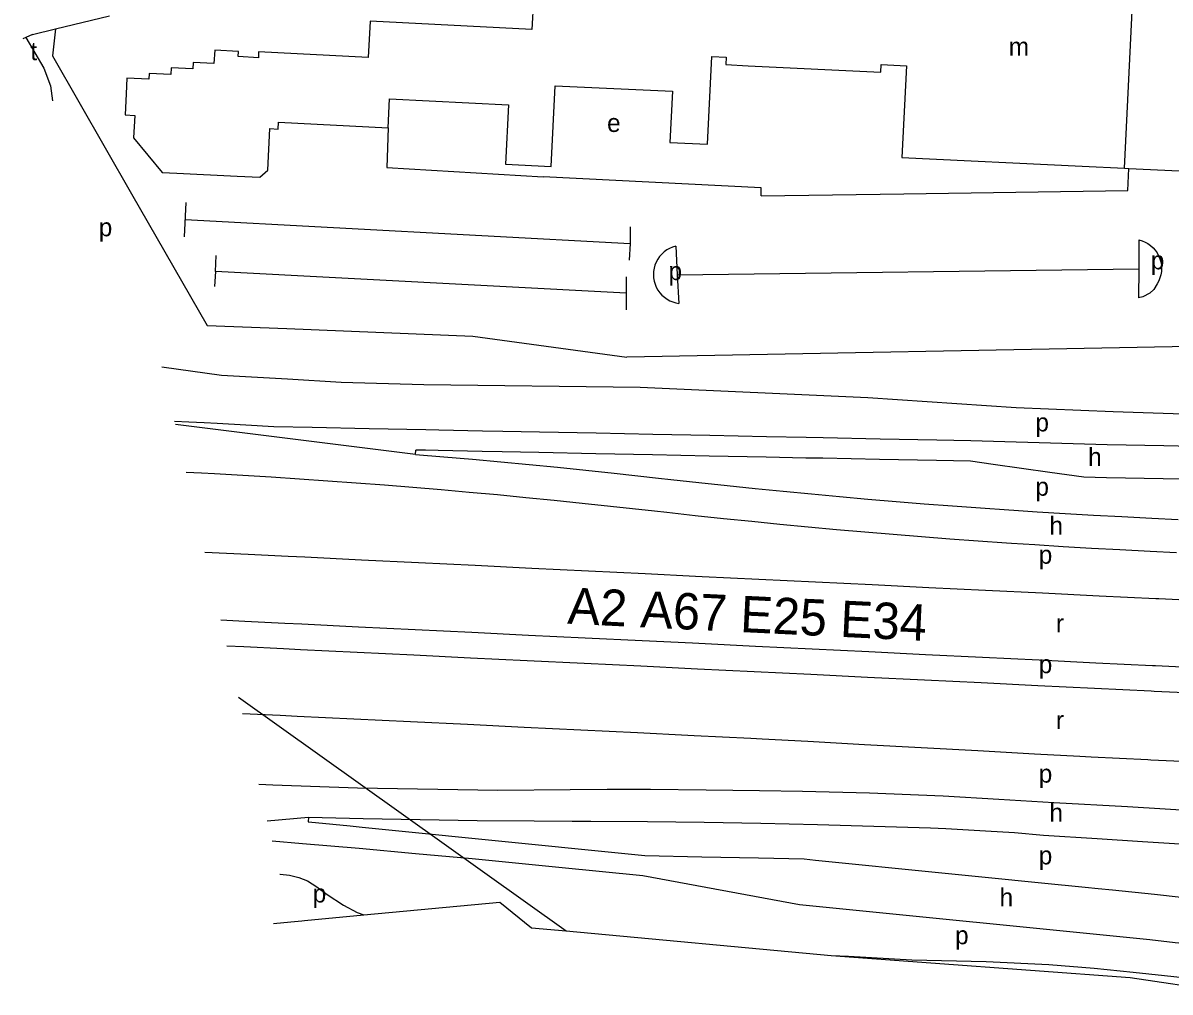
# Model space of a CAD drawing. Extents: x 161093 to 163177, y 379000 to 380904.
# Drawn here: x 161198.6 to 161451, y 379514.3 to 379727.5 of the extents above; entities that cross this region are included whole.
import ezdxf

# ---------------------------------------------------------------- set-up
doc = ezdxf.new("R2010")
doc.units = 0
for name, color, linetype in [('BLT_Basislijn', 7, 'Continuous'), ('BLT_Bebouwing', 7, 'Continuous'), ('BLT_Centroide', 7, 'Continuous'), ('BLT_Gemeentegrens', 7, 'Continuous'), ('BLT_Hoogspanningsmast_en_leidingen', 7, 'Continuous'), ('BLT_Onderdoorgang_en_onderverdeling', 7, 'Continuous'), ('BLT_Straatnaam_hoofdweg', 7, 'Continuous'), ('BLT_Vlakafsluiter', 7, 'Continuous')]:
    doc.layers.add(name, color=color, linetype=linetype)

msp = doc.modelspace()

# ---------------------------------------------------------------- linework, layer by layer
at = {"layer": 'BLT_Basislijn'}
for p, q in [((161205.69, 379726.17), (161217.61, 379729.09)), ((161200.69, 379724.95), (161205.69, 379726.17)), ((161199.17, 379724.28), (161198.56, 379724)), ((161200.69, 379724.95), (161199.17, 379724.28)), ((161361.02, 379689.46), (161392.42, 379689.88)), ((161234.4, 379688.04), (161234.08, 379680.46)), ((161234.28, 379684.25), (161332.2, 379679.02)), ((161332.22, 379682.62), (161332.2, 379679.02)), ((161332.2, 379679.02), (161332.01, 379675.35)), ((161342.24, 379678.39), (161342.59, 379672.11)), ((161444.19, 379679.79), (161444.16, 379673.43)), ((161342.59, 379672.11), (161444.16, 379673.43)), ((161444.16, 379673.43), (161444.12, 379667.07)), ((161240.91, 379672.82), (161240.71, 379669.5)), ((161331.36, 379671.66), (161331.34, 379668.05)), ((161342.59, 379672.11), (161342.93, 379665.82)), ((161331.34, 379668.05), (161331.32, 379664.43)), ((161284.94, 379632.59), (161285.02, 379633.53))]:
    msp.add_line(p, q, dxfattribs=at)
for points in [[(161205.69, 379726.17), (161205.1, 379720.28), (161222.47, 379689.88)], [(161199.17, 379724.28), (161203.13, 379717.53), (161204.65, 379713.67), (161205.1, 379710.37)], [(161278.96, 379704.45), (161278.68, 379695.69), (161313.06, 379693.67)], [(161361.02, 379689.46), (161361.02, 379691.26), (161313.06, 379693.67)], [(161392.42, 379689.88), (161441.74, 379690.61), (161441.93, 379695.52)], [(161222.47, 379689.88), (161239.14, 379660.92), (161256.65, 379660.27)], [(161342.24, 379678.39), (161341.55, 379678.19), (161340.89, 379677.91), (161340.27, 379677.56), (161339.69, 379677.14), (161339.16, 379676.66), (161338.69, 379676.12), (161338.28, 379675.54), (161337.93, 379674.91), (161337.67, 379674.25), (161337.47, 379673.56), (161337.35, 379672.86), (161337.32, 379672.14), (161337.36, 379671.43), (161337.48, 379670.72), (161337.68, 379670.04), (161337.96, 379669.38), (161338.31, 379668.75), (161338.72, 379668.17), (161339.2, 379667.64), (161339.73, 379667.16), (161340.32, 379666.75), (161340.94, 379666.4), (161341.61, 379666.13), (161342.29, 379665.93), (161342.93, 379665.82)], [(161444.19, 379679.79), (161444.88, 379679.59), (161445.54, 379679.31), (161446.17, 379678.96), (161446.75, 379678.54), (161447.29, 379678.06), (161447.77, 379677.52), (161448.18, 379676.93), (161448.53, 379676.3), (161448.8, 379675.64), (161449, 379674.95), (161449.12, 379674.24), (161449.17, 379673.52), (161449.13, 379672.8), (161449.01, 379672.1), (161448.82, 379671.4), (161448.54, 379670.74), (161448.2, 379670.11), (161447.45, 379668.85), (161446.59, 379668.04), (161445.08, 379667.22), (161444.12, 379667.07)], [(161331.34, 379668.05), (161240.91, 379672.82), (161241.1, 379676.36)], [(161256.65, 379660.27), (161297.56, 379658.59), (161331.45, 379654.01)], [(161455.37, 379656.3), (161331.45, 379654.01)], [(161229.14, 379651.85), (161242.26, 379650.05), (161256.79, 379649.21)], [(161256.79, 379649.21), (161268.61, 379648.52), (161286.79, 379647.95), (161334.43, 379647.41), (161384.55, 379645.12), (161417.14, 379642.88), (161438.53, 379642.04), (161456.14, 379641.47), (161472.44, 379640.15), (161475.32, 379639.71), (161477.25, 379638.79)], [(161462.19, 379634.21), (161449.69, 379634.47), (161437.2, 379634.72), (161432.2, 379634.82), (161424.7, 379635.04), (161412.21, 379635.42), (161407.21, 379635.57), (161399.71, 379635.72), (161387.21, 379635.97), (161374.71, 379636.23), (161370.93, 379636.3), (161362.22, 379636.48), (161349.72, 379636.73), (161337.22, 379636.98), (161324.72, 379637.23), (161312.23, 379637.48), (161304.15, 379637.65), (161299.73, 379637.74), (161290.07, 379637.93), (161287.23, 379637.99), (161274.73, 379638.24), (161262.24, 379638.49), (161253.81, 379638.66), (161247.61, 379639.04), (161241.33, 379639.4), (161238.46, 379639.53), (161235.05, 379639.68), (161231.94, 379639.81)], [(161284.94, 379632.59), (161291.23, 379632.07), (161297.48, 379631.52), (161303.73, 379630.95), (161309.97, 379630.36), (161316.22, 379629.75), (161322.46, 379629.11), (161328.7, 379628.45), (161338.41, 379627.37), (161341.15, 379627.06), (161347.34, 379626.38), (161353.53, 379625.72), (161359.72, 379625.09), (161365.92, 379624.48), (161372.11, 379623.89), (161378.31, 379623.32), (161384.51, 379622.78), (161390.72, 379622.25), (161396.92, 379621.75), (161403.13, 379621.28), (161409.34, 379620.83), (161415.55, 379620.4), (161416.69, 379620.32), (161421.76, 379619.99), (161427.97, 379619.6), (161434.19, 379619.24), (161440.4, 379618.9), (161447.03, 379618.57), (161452.86, 379618.28)], [(161486.32, 379626.53), (161483.91, 379626.53), (161474.54, 379626.71), (161462.05, 379626.97), (161449.55, 379627.22), (161437.05, 379627.47), (161432.05, 379627.57), (161424.57, 379628.62), (161412.1, 379630.37), (161407.12, 379631.07), (161399.62, 379631.22), (161387.12, 379631.48), (161374.62, 379631.73), (161370.84, 379631.8), (161362.13, 379631.98), (161349.63, 379632.23), (161337.13, 379632.48), (161324.63, 379632.73), (161312.14, 379632.99), (161304.06, 379633.15), (161299.64, 379633.24), (161289.98, 379633.43), (161287.14, 379633.49), (161285.02, 379633.53)], [(161234.52, 379628.71), (161237.86, 379628.53), (161240.72, 379628.37), (161246.95, 379628.01), (161253.19, 379627.63), (161259.42, 379627.22), (161265.66, 379626.79), (161271.89, 379626.34), (161278.12, 379625.87), (161284.35, 379625.37), (161290.58, 379624.85), (161296.8, 379624.3), (161303.02, 379623.74), (161309.24, 379623.15), (161315.46, 379622.53), (161321.68, 379621.9), (161327.89, 379621.24), (161337.56, 379620.17), (161340.31, 379619.86), (161346.53, 379619.18), (161352.74, 379618.52), (161358.96, 379617.88), (161365.18, 379617.26), (161371.41, 379616.67), (161377.63, 379616.1), (161383.86, 379615.55), (161390.09, 379615.03), (161396.32, 379614.53), (161402.56, 379614.05), (161408.79, 379613.6), (161415.03, 379613.16), (161416.17, 379613.09), (161421.27, 379612.75), (161427.51, 379612.37), (161433.75, 379612), (161439.99, 379611.66), (161446.65, 379611.33), (161452.47, 379611.04)], [(161238.61, 379611.1), (161248.14, 379610.64), (161256.91, 379610.21), (161260.62, 379610.03), (161273.11, 379609.42), (161285.59, 379608.81), (161298.08, 379608.21), (161310.56, 379607.6), (161323.05, 379606.99), (161335.53, 379606.38), (161346.62, 379605.84), (161348.02, 379605.77), (161360.51, 379605.16), (161372.99, 379604.55), (161385.48, 379603.95), (161397.96, 379603.34), (161410.45, 379602.73), (161422.93, 379602.12), (161435.42, 379601.51), (161447.9, 379600.9), (161448.56, 379600.87), (161460.39, 379600.29), (161470.55, 379599.8)], [(161242.08, 379596.17), (161247.42, 379595.91), (161256.19, 379595.48), (161259.91, 379595.3), (161272.39, 379594.69), (161284.88, 379594.08), (161297.36, 379593.47), (161309.85, 379592.86), (161322.33, 379592.26), (161334.82, 379591.65), (161345.9, 379591.11), (161347.3, 379591.04), (161359.79, 379590.43), (161372.27, 379589.82), (161384.76, 379589.21), (161397.24, 379588.61), (161409.73, 379588), (161422.21, 379587.39), (161434.7, 379586.78), (161447.18, 379586.17), (161447.84, 379586.14), (161459.67, 379585.56), (161468.18, 379585.15)], [(161243.4, 379590.5), (161247.15, 379590.31), (161255.92, 379589.89), (161259.63, 379589.71), (161272.12, 379589.1), (161284.6, 379588.49), (161297.09, 379587.88), (161309.57, 379587.27), (161322.06, 379586.66), (161334.54, 379586.05), (161345.63, 379585.51), (161347.03, 379585.45), (161359.51, 379584.84), (161372, 379584.23), (161384.48, 379583.62), (161396.97, 379583.01), (161409.46, 379582.4), (161421.94, 379581.79), (161434.43, 379581.19), (161446.91, 379580.58), (161447.57, 379580.55), (161459.4, 379579.97), (161467.42, 379579.58)], [(161465.01, 379564.48), (161458.66, 379564.79), (161446.83, 379565.36), (161446.17, 379565.4), (161433.69, 379566), (161431.19, 379566.13), (161421.2, 379566.68), (161408.72, 379567.37), (161396.24, 379568.05), (161383.76, 379568.74), (161371.28, 379569.43), (161361.29, 379569.98), (161358.8, 379570.1), (161346.31, 379570.71), (161344.91, 379570.78), (161333.83, 379571.32), (161321.34, 379571.93), (161308.86, 379572.54), (161296.37, 379573.15), (161283.89, 379573.76), (161271.4, 379574.36), (161258.91, 379574.97), (161255.2, 379575.15), (161246.87, 379575.56)], [(161468.91, 379553.37), (161441.66, 379555.1), (161425.48, 379555.97), (161413.37, 379556.65), (161401.07, 379557.43), (161384.91, 379558.08), (161370.17, 379558.47), (161360.71, 379558.61), (161348.9, 379558.77), (161336.72, 379558.86), (161327.12, 379558.86), (161319.01, 379558.78), (161303.08, 379558.68), (161272.2, 379559.16), (161253.53, 379559.85), (161250.49, 379560.01)], [(161261.39, 379552.8), (161261.36, 379551.8), (161262.93, 379551.64), (161270.59, 379550.87), (161273.23, 379550.61), (161285.67, 379549.36), (161298.11, 379548.11), (161310.54, 379546.87), (161322.98, 379545.62), (161335.42, 379544.37), (161347.96, 379544.1), (161360.49, 379543.83), (161370.52, 379543.61), (161373.01, 379543.36), (161385.44, 379542.12), (161388.3, 379541.83), (161397.88, 379540.87), (161410.32, 379539.62), (161422.76, 379538.38), (161432.34, 379537.41), (161435.2, 379537.13), (161438.37, 379536.81), (161447.63, 379535.88), (161453.48, 379535.19)], [(161261.39, 379552.8), (161273.45, 379552.5), (161285.98, 379552.25), (161298.52, 379552.08), (161311.06, 379551.98), (161319.42, 379551.95), (161323.57, 379551.94), (161336.03, 379551.86), (161348.49, 379551.72), (161360.95, 379551.5), (161373.41, 379551.21), (161385.87, 379550.85), (161398.32, 379550.42), (161401.66, 379550.29), (161410.39, 379549.77), (161416.83, 379549.4), (161423.22, 379548.85), (161435.02, 379548.07), (161444.96, 379547.48), (161454.4, 379546.86), (161462.23, 379546.44), (161464.09, 379546.35)], [(161466.57, 379523.58), (161465.52, 379523.74), (161459.11, 379524.48), (161452.14, 379525.12), (161446.62, 379525.78), (161369.51, 379533.51), (161334.97, 379539.89), (161316.52, 379541.74), (161309.87, 379542.4), (161297.43, 379543.61), (161284.98, 379544.76), (161272.54, 379545.87), (161260.08, 379546.94), (161253.4, 379547.49)], [(161255.08, 379540.24), (161255.15, 379540.25), (161257.25, 379540.03), (161259.25, 379539.55), (161261.18, 379538.79), (161263.23, 379537.45), (161265.49, 379535.78), (161269.15, 379533.41), (161272.11, 379531.85), (161273.62, 379531.29)], [(161376.44, 379522.39), (161380.29, 379522.21), (161394.19, 379521.43), (161410.58, 379521.06), (161424.33, 379520.4), (161434.31, 379519.55), (161442.93, 379518.71), (161458.75, 379517.04)]]:
    msp.add_lwpolyline(points, dxfattribs=at)
at = {"layer": 'BLT_Bebouwing'}
for p, q in [((161221.43, 379715.34), (161221.27, 379711.93)), ((161278.96, 379704.45), (161279.27, 379710.84)), ((161229.17, 379694.61), (161232.4, 379694.45)), ((161232.4, 379694.45), (161245.7, 379693.82)), ((161441.02, 379695.56), (161441.93, 379695.52))]:
    msp.add_line(p, q, dxfattribs=at)
for points in [[(161441.93, 379695.52), (161465.67, 379694.42), (161467.94, 379740.95), (161466.38, 379741.02)], [(161335.09, 379733.57), (161334.97, 379731.37), (161310.9, 379732.54), (161310.58, 379726.03), (161274.95, 379727.86), (161274.55, 379719.9), (161250.44, 379721.14), (161250.37, 379719.86), (161245.93, 379720.09), (161245.98, 379721.22), (161240.76, 379721.48), (161240.61, 379718.55), (161236.02, 379718.78), (161235.95, 379717.43), (161231.21, 379717.66), (161231.14, 379716.17), (161226.33, 379716.4), (161226.26, 379715.11), (161221.43, 379715.34)], [(161279.27, 379710.84), (161305.4, 379709.51), (161304.74, 379696.42), (161314.84, 379695.95), (161315.71, 379713.69), (161341.51, 379712.5), (161340.96, 379701.2), (161349.25, 379700.8), (161350.19, 379720.15), (161353.32, 379720), (161353.24, 379718.33), (161358.2, 379718.08), (161387.35, 379716.64), (161387.43, 379718.36), (161393.02, 379718.1), (161392.03, 379697.89)], [(161221.27, 379711.93), (161221.04, 379707.26), (161223.15, 379707.15), (161222.91, 379702.2), (161229.17, 379694.61)], [(161252.45, 379695.14), (161252.89, 379704.25), (161254.75, 379704.16), (161254.83, 379705.65), (161278.96, 379704.45)], [(161392.03, 379697.89), (161431.7, 379695.99), (161441.02, 379695.56)], [(161245.7, 379693.82), (161250.68, 379693.58), (161252.45, 379695.14)]]:
    msp.add_lwpolyline(points, dxfattribs=at)
at = {"layer": 'BLT_Gemeentegrens'}
for points in [[(161273.62, 379531.29), (161303.54, 379534.1), (161310.47, 379528.49), (161318.14, 379527.78), (161376.44, 379522.39)], [(161253.69, 379529.42), (161257.51, 379529.78), (161259.95, 379530.01), (161260.53, 379530.06), (161273.62, 379531.29)], [(161376.44, 379522.39), (161442.23, 379517.53), (161462.01, 379514.56), (161462.95, 379514.33)]]:
    msp.add_lwpolyline(points, dxfattribs=at)
at = {"layer": 'BLT_Hoogspanningsmast_en_leidingen'}
msp.add_line((161246.03, 379579.21), (161318.14, 379527.78), dxfattribs=at)
msp.add_line((161246.03, 379579.21), (161318.14, 379527.78), dxfattribs=at)
at = {"layer": 'BLT_Onderdoorgang_en_onderverdeling'}
msp.add_lwpolyline([(161441.02, 379695.56), (161443.22, 379740.71), (161442.71, 379740.73)], dxfattribs=at)
at = {"layer": 'BLT_Vlakafsluiter'}
for p, q in [((161284.94, 379632.59), (161232.1, 379639.14)), ((161252.34, 379552.02), (161261.39, 379552.8))]:
    msp.add_line(p, q, dxfattribs=at)

# ---------------------------------------------------------------- texts
at = {"layer": 'BLT_Centroide'}
for s, p in [('m', (161415.54, 379720.3)), ('t', (161200.21, 379719.3)), ('e', (161327.13, 379703.52)), ('p', (161215.25, 379680.57)), ('p', (161446.81, 379673.3)), ('p', (161340.66, 379670.94)), ('p', (161421.41, 379637.65)), ('h', (161433.01, 379630.04)), ('p', (161421.41, 379623.5)), ('h', (161424.49, 379614.93)), ('p', (161422.14, 379608.54)), ('r', (161425.91, 379593.44)), ('p', (161422.14, 379584.46)), ('r', (161425.91, 379572.16)), ('p', (161422.14, 379560.39)), ('h', (161424.49, 379551.8)), ('p', (161422.14, 379542.4)), ('p', (161262.34, 379534.03)), ('h', (161413.53, 379533.16)), ('p', (161403.73, 379524.84))]:
    msp.add_text(s, height=4, dxfattribs=at).set_placement(p)
at = {"layer": 'BLT_Straatnaam_hoofdweg'}
msp.add_text('A2 A67 E25 E34', height=8, rotation=357.2457, dxfattribs=at).set_placement((161318.3, 379595.36))

doc.saveas('drawing.dxf')
